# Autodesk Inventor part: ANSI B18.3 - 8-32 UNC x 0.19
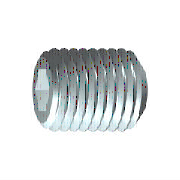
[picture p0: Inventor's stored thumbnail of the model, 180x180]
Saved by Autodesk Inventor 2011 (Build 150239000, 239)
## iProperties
IsCustomPart: 0
Created: 2008-02
Part Number: ANSI B18.3 - 8-32 UNC x 0.19
Material: Steel, Mild
Description: Hexagon Socket Set Screw - Flat Point
Document SubType Name: Modeling
Standard: ANSI B18.3
Standard Revision: 2003
Standards Organization: ANSI
Language: en-US
Size Designation: 8-32 UNC x 0.19
Categories: <MemberInstance><Categories><Category DisplayName="Fasteners" InternalName="e4da775c-781d-43d5-af7c-5136215cf5a6" Mnemonic="FSTN"><Category DisplayName="Bolts"
Density: 1 g/cm^3
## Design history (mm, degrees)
revolve "Body" stored, may be unused: angle "d6" = 90 deg
sketch "Sketch2"
  geometry: L1 (-0.572, 0.991)-(0.572, 0.991); L2 (0.572, 0.991)-(1.144, 0); L3 (1.144, 0)-(0.572, -0.991); L4 (0.572, -0.991)-(-0.572, -0.991); L5 (-0.572, -0.991)-(-1.144, 0); L6 (-1.144, 0)-(-0.572, 0.991); A1 r 1.144 centre (0, 0) between (-0.572, 0.991) and (0.572, 0.991) reference; 2 further points
  constraints: 12 end point, 2 point on circle, 1 coincident, 1 horizontal, 11 other
extrude "Slot" join sketch "Sketch2" taper "d9" = 0 deg; stored distance "d21" = 10
workaxis "Work Axis1"
workplane "Work Plane1"
body "Solid1"
chamfer "Chamfer1" distance "d7" = 0.48691 (= -0.5 x GD1 + 0.5 x NND); stored, may be unused: angle "d8" = 45 deg (= FAWI), second distance "d29" = 0.48691 (= -0.5 x GD1 + 0.5 x NND)
feature "Thread" dims "d11" = 4.826 (= NLG), "d12" = 0
chamfer "Chamfer2" distance "d13" = 0.48691 (= -0.5 x GD1 + 0.5 x NND); stored, may be unused: angle "d14" = 45 deg (= FAWI), second distance "d30" = 0.48691 (= -0.5 x GD1 + 0.5 x NND)
sketch "Sketch1"
  geometry: L1 (0, 0)-(1.88, 0); L2 (4.826, 1.144)-(4.826, 2.083); L3 (4.826, 2.083)-(0, 2.083); L4 (4.826, 1.144)-(2.54, 1.144); L5 (2.54, 1.144)-(1.88, 0); L6 (0, -0.417)-(0, 2.499) reference; L7 (0, 2.083)-(0, 0)
  constraints: 13 end point, 3 parallel, 1 collinear, 1 perpendicular, 1 point on line
  dimensions: "d0" = 2.286 distance of L2.start L4.end (= INTI); "d1" = 60 deg angle of L5 L1; "d2" = 4.1656 diameter of L3 L1 (= NND); "d3" = 2.28769 diameter of L4 L1 (= 1.1547 x SW); "d5" = 4.826 distance from line of L2 L3.end (= NLG)
other parameters: "NND" = 4.1656 [user parameter; used in 5 equation terms], "NLG" = 4.826 [user parameter; used in 2 equation terms], "INTI" = 2.286 [user parameter; used in 1 equation term], "FAWI" = 45 deg [user parameter; used in 3 equation terms], "SW" = 1.9812 [user parameter; used in 2 equation terms], "GD1" = 3.19177 [user parameter; used in 4 equation terms], "d4" = 0, "FAWI1" = 45 deg (= FAWI) [user parameter], "d15" = 0, "d31" = 0, "SPD" = 2.2098 [user parameter], "SEWI" = 90 deg [user parameter], "TOA" = 30 deg [user parameter], "ZLG" = 1.0922 [user parameter], "ZD" = 2.7686 [user parameter], "HHPTC" = 0.79375 [user parameter], "PTC" = 0.79375 (computed from TPU) [user parameter], "THREADDIA" = 4.1656 [user parameter], "OPR" = 3.1242 [user parameter], "E0" = 2.28829 (= 1.155 x SW) [user parameter]
